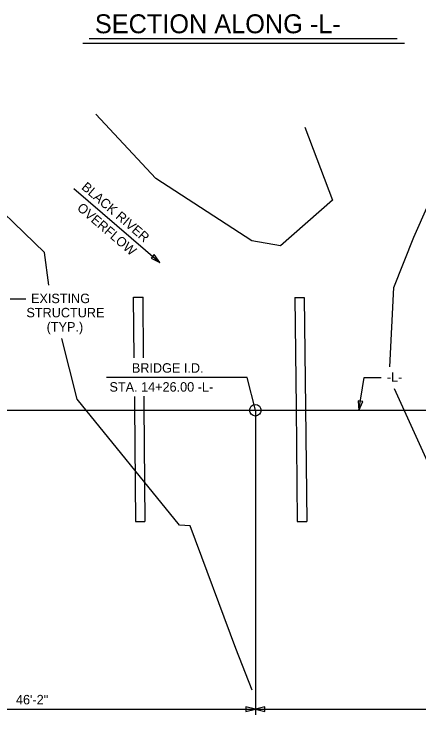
# Model space of a CAD drawing. Extents: x 471 to 2034, y -623 to 126.
# Drawn here: x 661.5 to 704.3, y -53.3 to 20.8 of the extents above; entities that cross this region are included whole.
import ezdxf

# ---------------------------------------------------------------- set-up
doc = ezdxf.new("R2010")
doc.units = 0
for name, color, linetype in [('Arrowhead Terminators CELL', 7, 'Continuous'), ('Auto Dimensioning', 7, 'Continuous'), ('Dimension Lines', 7, 'Continuous'), ('Exist Hydro Stream or Body of Water', 7, 'Continuous'), ('Exist Structure Major Bridge Seam', 7, 'Continuous'), ('Prop Horizontal Alignment', 7, 'Continuous'), ('Title Text', 7, 'Continuous')]:
    doc.layers.add(name, color=color, linetype=linetype)

msp = doc.modelspace()

# ---------------------------------------------------------------- linework, layer by layer
at = {"layer": 'Arrowhead Terminators CELL'}
for points in [[(676.895, -5.411), (676.298, -4.57), (675.973, -4.95)], [(697.942, -21.027), (698.348, -20.079), (697.854, -20)], [(686.989, -52.568), (685.989, -52.318), (685.989, -52.818)], [(686.989, -52.568), (687.989, -52.818), (687.989, -52.318)]]:
    msp.add_lwpolyline(points, close=True, dxfattribs=at)
at = {"layer": 'Auto Dimensioning'}
for p, q in [((640.824, -52.568), (686.989, -52.568)), ((686.989, -52.568), (733.154, -52.568))]:
    msp.add_line(p, q, dxfattribs=at)
at = {"layer": 'Dimension Lines'}
for p, q in [((667.781, 2.394), (676.895, -5.411)), ((661.044, -9.229), (662.719, -9.229)), ((686.115, -17.546), (671.236, -17.546)), ((686.989, -21.012), (686.115, -17.546)), ((697.942, -21.027), (698.502, -17.546)), ((698.502, -17.546), (700.304, -17.546)), ((686.989, -21.012), (686.989, -53.166))]:
    msp.add_line(p, q, dxfattribs=at)
msp.add_circle((686.989, -21.012), 0.606, dxfattribs=at)
at = {"layer": 'Exist Hydro Stream or Body of Water'}
for points in [[(692.221, 8.893), (695.145, 1.174), (689.661, -3.652), (686.601, -3.139), (676.457, 3.444), (670.118, 10.242)], [(701.205, -16.441), (701.623, -8.065), (703.736, -2.726), (709.379, 9.974)], [(665.153, -7.815), (664.7, -4.37), (657.068, 2.96)], [(686.632, -50.582), (684.923, -46.167), (680.095, -33.205), (678.976, -33.13), (668.142, -19.832), (666.52, -13.443)], [(720.234, -59.995), (712.935, -45.678), (708.822, -37.305), (707.974, -37.243), (707.877, -32.29), (701.705, -18.741)]]:
    msp.add_lwpolyline(points, dxfattribs=at)
at = {"layer": 'Exist Structure Major Bridge Seam'}
for p, q in [((674.114, -9.077), (675.114, -9.077)), ((674.165, -15.484), (674.114, -9.077)), ((675.165, -15.476), (675.114, -9.077)), ((691.158, -9.111), (692.158, -9.111)), ((674.306, -32.74), (675.306, -32.74)), ((691.416, -32.774), (692.416, -32.774))]:
    msp.add_line(p, q, dxfattribs=at)
for points in [[(691.158, -9.111), (691.285, -20.729), (691.416, -32.774)], [(692.158, -9.111), (692.285, -20.729), (692.416, -32.774)], [(674.198, -19.544), (674.206, -20.551), (674.306, -32.74)], [(675.198, -19.536), (675.206, -20.551), (675.306, -32.74)]]:
    msp.add_lwpolyline(points, dxfattribs=at)
at = {"layer": 'Prop Horizontal Alignment'}
msp.add_line((657.095, -21.012), (717.006, -21.012), dxfattribs=at)
at = {"layer": 'Title Text'}
for p, q in [((669.416, 18.258), (701.997, 18.258)), ((668.735, 17.758), (702.772, 17.758))]:
    msp.add_line(p, q, dxfattribs=at)

# ---------------------------------------------------------------- texts
at = {"layer": 'Dimension Lines'}
for s, p in [('BLACK RIVER', (668.524, 2.417)), ('OVERFLOW', (668.052, 0.221))]:
    msp.add_text(s, height=1, rotation=319.42413, dxfattribs=at).set_placement(p)
for s, p in [('EXISTING', (663.262, -9.702)), ('STRUCTURE', (662.777, -11.202)), ('(TYP.)', (664.915, -12.702)), ('BRIDGE I.D.', (673.93, -17.046)), ('-L-', (700.898, -17.999)), ('STA. 14+26.00 -L-', (671.56, -19.046)), ('46\'-2"', (661.675, -52.068))]:
    msp.add_text(s, height=1, dxfattribs=at).set_placement(p)
at = {"layer": 'Title Text'}
msp.add_text('SECTION ALONG -L-', height=2, dxfattribs=at).set_placement((670.016, 18.795))

doc.saveas('drawing.dxf')
